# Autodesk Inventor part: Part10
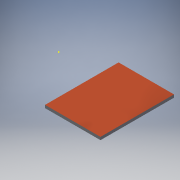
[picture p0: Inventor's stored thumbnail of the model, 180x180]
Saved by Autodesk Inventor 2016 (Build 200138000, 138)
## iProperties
Created: 2020-04
Part Number: Part10
Material: Generic
Document SubType Name: Modeling
Designer: merlin
Density: 1 g/cm^3
Appearance: Default
Author: merlin
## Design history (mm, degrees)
sketch "Sketch1"
  geometry: L1 (-174.625, 234.95)-(-422.275, 234.95); L2 (-422.275, 234.95)-(-422.275, -93.663); L3 (-422.275, -93.663)-(-174.625, -93.663); L4 (-174.625, -93.663)-(-174.625, 234.95); 1 further point
  constraints: 8 end point, 2 parallel, 1 horizontal, 1 perpendicular
extrude "Extrusion1" new body sketch "Sketch1" distance "d0" = 12.7; taper "d1" = 0 deg
sketch "Sketch2"
  geometry: 1 further point
body "Solid1"
